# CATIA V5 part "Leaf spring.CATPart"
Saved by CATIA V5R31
Part number: Part1
Material "Steel": density 7860 kg/m3, Young's modulus 2e+11 Pa, Poisson ratio 0.266, thermal expansion 1.17e-05 1/K
Bounding box of the stored display mesh (mm): x 0 to 6, y -52.464 to 52.464, z -1 to 10.425
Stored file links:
  D:\PROJECTS\Project 2021\US EDITION\CATIA V5 6R 2021\Resources\Tutorial Files\c19_catia_v5_6r2021_tut\C19_tut_03.CATPart\Leaf spring.CATPart
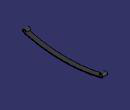
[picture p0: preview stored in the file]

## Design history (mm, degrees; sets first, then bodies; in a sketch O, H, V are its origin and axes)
Body1 (main body), material "Steel"
  Sketch1 on yz-plane, origin (0, 0, 0), H (0, 1, 0), V (0, 0, 1)
    arc A1 centre (0, 199) radius 199 from (-50.3797, 6.4828) to (50.3797, 6.4828) ccw
    point P1 (0, 199)
    arc A2 centre (0, 199) radius 200 from (-50.6329, 5.5154) to (50.6329, 5.5154) ccw
    arc A3 centre (-50, 7.9339) radius 2.5 from (-47.5, 7.9339) to (-50.6329, 5.5154) ccw
    point P2 (-50, 7.9339)
    arc A4 centre (50, 7.9339) radius 2.5 from (47.5, 7.9339) to (50.6329, 5.5154) cw
    arc A5 centre (-50, 7.9339) radius 1.5 from (-48.5, 7.9339) to (-50.3797, 6.4828) ccw
    point P4 (50, 7.9339)
    arc A6 centre (50, 7.9339) radius 1.5 from (48.5, 7.9339) to (50.3797, 6.4828) cw
    point P8 (50.3797, 6.4828)
    line L1 (48.5, 7.9339) -> (47.5, 7.9339)
    point P10 (-47.5, 7.9339)
    point P11 (50.3797, 6.4828)
    line L2 (-47.5, 7.9339) -> (-48.5, 7.9339)
    distance A1 A2 = 1
    distance P4 P2 = 100
    radius A3 = 2.5
    radius A2 = 200
    coincidence: A1 O, P1 V, A6 P8, L1 P10, A1 P11, L1 L2, L2 P2
    concentricity: A1 A2
    tangency: A3 A2, A5 A1
    symmetry: A3 A4 V, A5 A6 V
    horizontal: L1 H, L2 H
  Pad1: profile Sketch1, direction (1, 0, 0), length 6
